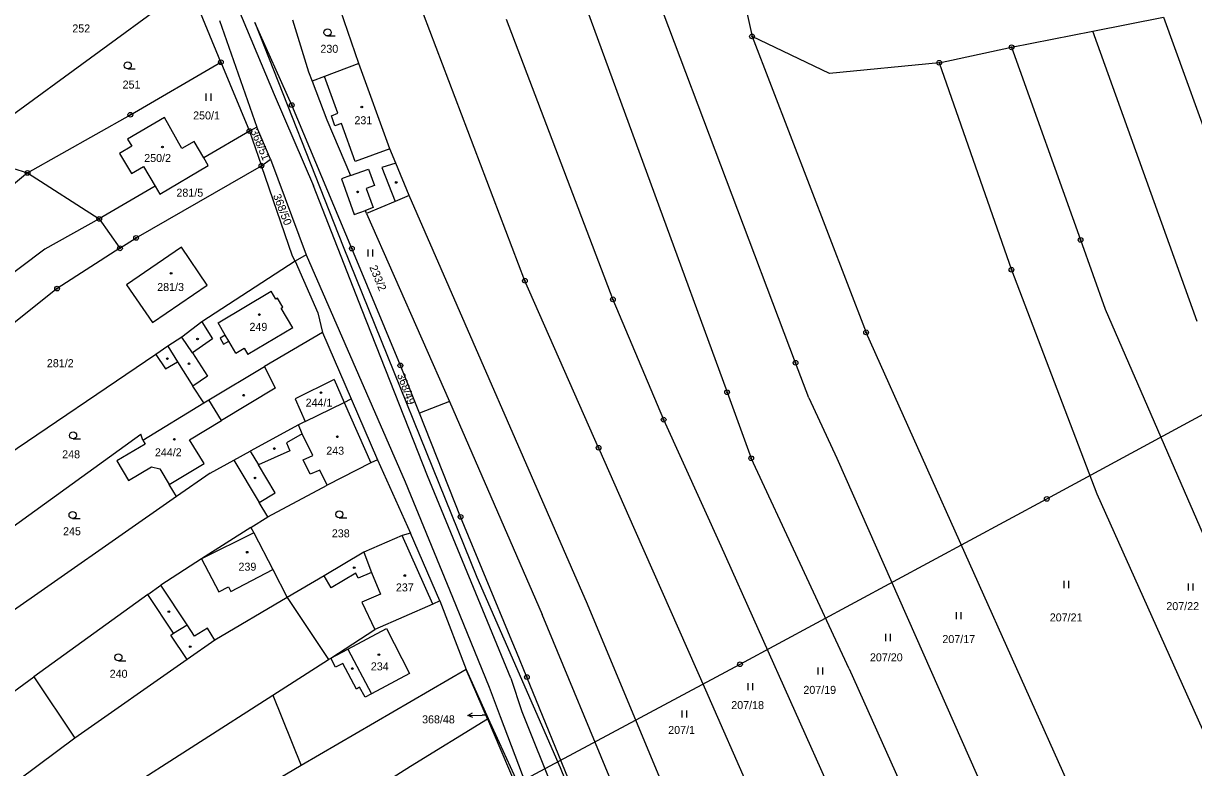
# Model space of a CAD drawing. Extents: x -762263 to -760336, y -1154405 to -1152076.
# Drawn here: x -761541.7 to -761293.1, y -1152788.2 to -1152630.1 of the extents above; entities that cross this region are included whole.
import ezdxf

# ---------------------------------------------------------------- set-up
doc = ezdxf.new("R2010")
doc.units = 0
for name, color, linetype in [('Vrstva 1', 7, 'Continuous'), ('Vrstva 12', 7, 'Continuous'), ('Vrstva 16', 7, 'Continuous'), ('Vrstva 18', 7, 'Continuous'), ('Vrstva 19', 7, 'Continuous'), ('Vrstva 24', 7, 'Continuous'), ('Vrstva 25', 7, 'Continuous'), ('Vrstva 26', 7, 'Continuous'), ('Vrstva 4', 7, 'Continuous'), ('Vrstva 6', 7, 'Continuous')]:
    doc.layers.add(name, color=color, linetype=linetype)

msp = doc.modelspace()

# ---------------------------------------------------------------- linework, layer by layer
at = {"layer": 'Vrstva 1'}
for p, q in [((-761506.46, -1152622.12), (-761545.06, -1152650.41)), ((-761499.73, -1152638.35), (-761506.46, -1152622.12)), ((-761470.41, -1152638.61), (-761474.34, -1152627.29)), ((-761484.68, -1152647.45), (-761492.49, -1152629.91)), ((-761492.49, -1152629.91), (-761473.79, -1152677.53)), ((-761484.52, -1152629.33), (-761481.11, -1152640.38)), ((-761518.97, -1152649.52), (-761499.73, -1152638.35)), ((-761499.73, -1152638.35), (-761493.66, -1152653)), ((-761470.41, -1152638.61), (-761477.69, -1152641.39)), ((-761463.81, -1152656.76), (-761470.41, -1152638.61)), ((-761481.11, -1152640.38), (-761480.35, -1152642.4)), ((-761477.69, -1152641.39), (-761480.35, -1152642.4)), ((-761480.35, -1152642.4), (-761477.25, -1152650.6)), ((-761471.9, -1152677.93), (-761484.68, -1152647.45)), ((-761540.81, -1152661.88), (-761518.97, -1152649.52)), ((-761511.7, -1152650.12), (-761519.55, -1152654.73)), ((-761508.02, -1152656.7), (-761511.7, -1152650.12)), ((-761477.25, -1152650.6), (-761472.2, -1152662.45)), ((-761493.66, -1152653), (-761503.38, -1152658.68)), ((-761492.09, -1152652.18), (-761493.66, -1152653)), ((-761493.66, -1152653), (-761491.13, -1152660.34)), ((-761489.17, -1152658.94), (-761492.09, -1152652.18)), ((-761519.55, -1152654.73), (-761518.68, -1152656.19)), ((-761505.4, -1152655.23), (-761508.02, -1152656.7)), ((-761503.38, -1152658.68), (-761505.4, -1152655.23)), ((-761554.48, -1152657.55), (-761540.81, -1152661.88)), ((-761518.68, -1152656.19), (-761521.29, -1152657.71)), ((-761521.29, -1152657.71), (-761518.76, -1152662.01)), ((-761462.56, -1152659.79), (-761463.81, -1152656.76)), ((-761518.76, -1152662.01), (-761516.17, -1152660.49)), ((-761517.74, -1152675.69), (-761491.13, -1152660.34)), ((-761516.17, -1152660.49), (-761513.7, -1152664.7)), ((-761512.73, -1152666.35), (-761502.42, -1152660.31)), ((-761502.42, -1152660.31), (-761503.38, -1152658.68)), ((-761491.13, -1152660.34), (-761489.17, -1152658.94)), ((-761484.52, -1152679.56), (-761491.13, -1152660.34)), ((-761489.17, -1152658.94), (-761481.59, -1152679.26)), ((-761459.73, -1152666.69), (-761462.56, -1152659.79)), ((-761540.81, -1152661.88), (-761525.57, -1152671.64)), ((-761472.2, -1152662.45), (-761474.13, -1152663.15)), ((-761474.13, -1152663.15), (-761471.39, -1152670.71)), ((-761513.7, -1152664.7), (-761525.57, -1152671.64)), ((-761513.7, -1152664.7), (-761512.73, -1152666.35)), ((-761462.71, -1152667.95), (-761468.8, -1152670.52)), ((-761459.73, -1152666.69), (-761462.71, -1152667.95)), ((-761421.84, -1152753.46), (-761459.73, -1152666.69)), ((-761471.39, -1152670.71), (-761469.04, -1152669.85)), ((-761468.8, -1152670.52), (-761469.04, -1152669.85)), ((-761468.8, -1152670.52), (-761451.14, -1152710.42)), ((-761525.57, -1152671.64), (-761521.17, -1152677.89)), ((-761521.17, -1152677.89), (-761517.74, -1152675.69)), ((-761521.17, -1152677.89), (-761534.53, -1152686.45)), ((-761508.11, -1152677.67), (-761519.77, -1152685.63)), ((-761502.62, -1152685.71), (-761508.11, -1152677.67)), ((-761473.79, -1152677.53), (-761445.33, -1152747.77)), ((-761461.61, -1152702.77), (-761471.9, -1152677.93)), ((-761483.96, -1152680.59), (-761503.77, -1152693.49)), ((-761483.96, -1152680.59), (-761484.52, -1152679.56)), ((-761481.59, -1152679.26), (-761483.96, -1152680.59)), ((-761483.96, -1152680.59), (-761479.15, -1152691.61)), ((-761519.77, -1152685.63), (-761514.27, -1152693.67)), ((-761514.27, -1152693.67), (-761502.62, -1152685.71)), ((-761534.53, -1152686.45), (-761560.58, -1152707.21)), ((-761479.15, -1152691.61), (-761478.16, -1152695.75)), ((-761503.77, -1152693.49), (-761508.04, -1152696.73)), ((-761478.16, -1152695.75), (-761490.45, -1152703.03)), ((-761478.16, -1152695.75), (-761472.08, -1152709.85)), ((-761508.04, -1152696.73), (-761510.99, -1152698.71)), ((-761513.57, -1152700.44), (-761563.12, -1152733.98)), ((-761510.99, -1152698.71), (-761513.57, -1152700.44)), ((-761513.57, -1152700.44), (-761511.51, -1152703.52)), ((-761511.51, -1152703.52), (-761508.97, -1152701.97)), ((-761508.97, -1152701.97), (-761505.66, -1152707.14)), ((-761502.27, -1152710.07), (-761490.45, -1152703.03)), ((-761457.57, -1152712.91), (-761461.61, -1152702.77)), ((-761503.36, -1152710.73), (-761505.66, -1152707.14)), ((-761516.34, -1152718.66), (-761503.36, -1152710.73)), ((-761503.36, -1152710.73), (-761502.27, -1152710.07)), ((-761499.64, -1152714.46), (-761502.27, -1152710.07)), ((-761481.83, -1152714.68), (-761473.56, -1152710.64)), ((-761473.56, -1152710.64), (-761472.08, -1152709.85)), ((-761472.08, -1152709.85), (-761466.43, -1152722.79)), ((-761451.14, -1152710.42), (-761457.57, -1152712.91)), ((-761451.14, -1152710.42), (-761431.48, -1152755.68)), ((-761448.8, -1152734.95), (-761457.57, -1152712.91)), ((-761506.42, -1152718.54), (-761499.64, -1152714.46)), ((-761483.25, -1152715.38), (-761493.53, -1152721)), ((-761481.83, -1152714.68), (-761483.25, -1152715.38)), ((-761555.22, -1152745.2), (-761516.73, -1152717.36)), ((-761516.34, -1152718.66), (-761516.73, -1152717.36)), ((-761515.84, -1152719.49), (-761521.87, -1152723.06)), ((-761516.34, -1152718.66), (-761515.84, -1152719.49)), ((-761503.32, -1152723.63), (-761506.42, -1152718.54)), ((-761521.87, -1152723.06), (-761519.36, -1152727.23)), ((-761502.03, -1152725.64), (-761496.96, -1152722.92)), ((-761496.96, -1152722.92), (-761493.53, -1152721)), ((-761496.96, -1152722.92), (-761491.61, -1152731.86)), ((-761466.43, -1152722.79), (-761467.9, -1152723.49)), ((-761466.43, -1152722.79), (-761459.46, -1152738.38)), ((-761519.36, -1152727.23), (-761514.47, -1152724.28)), ((-761514.47, -1152724.28), (-761512.72, -1152724.71)), ((-761512.72, -1152724.71), (-761510.71, -1152728.06)), ((-761510.71, -1152728.06), (-761503.32, -1152723.63)), ((-761502.03, -1152725.64), (-761509.17, -1152730.62)), ((-761467.9, -1152723.49), (-761477.17, -1152728.21)), ((-761509.17, -1152730.62), (-761510.71, -1152728.06)), ((-761509.17, -1152730.62), (-761546.71, -1152756.81)), ((-761489.77, -1152734.93), (-761477.17, -1152728.21)), ((-761489.77, -1152734.93), (-761491.61, -1152731.86)), ((-761493.34, -1152737.22), (-761489.77, -1152734.93)), ((-761437.9, -1152761.3), (-761448.8, -1152734.95)), ((-761493.34, -1152737.22), (-761503.85, -1152743.84)), ((-761493.34, -1152737.22), (-761492.77, -1152738.31)), ((-761492.77, -1152738.31), (-761488.69, -1152746.14)), ((-761461.22, -1152738.9), (-761469.36, -1152742.46)), ((-761459.46, -1152738.38), (-761461.22, -1152738.9)), ((-761453.19, -1152752.8), (-761459.46, -1152738.38)), ((-761469.36, -1152742.46), (-761477.8, -1152747.44)), ((-761503.85, -1152743.84), (-761512.5, -1152749.48)), ((-761488.69, -1152746.14), (-761485.62, -1152752.04)), ((-761477.8, -1152747.44), (-761485.62, -1152752.04)), ((-761445.33, -1152747.77), (-761427.68, -1152788.2)), ((-761515.26, -1152751.46), (-761512.5, -1152749.48)), ((-761515.26, -1152751.46), (-761539.5, -1152768.89)), ((-761509.8, -1152759.68), (-761515.26, -1152751.46)), ((-761485.62, -1152752.04), (-761500.99, -1152761.1)), ((-761485.62, -1152752.04), (-761476.85, -1152765.21)), ((-761453.19, -1152752.8), (-761454.73, -1152753.5)), ((-761453.19, -1152752.8), (-761447.62, -1152767.33)), ((-761454.73, -1152753.5), (-761467, -1152758.9)), ((-761359.06, -1152904.05), (-761421.84, -1152753.46)), ((-761365.51, -1152914.59), (-761431.48, -1152755.68)), ((-761510.34, -1152760.04), (-761509.8, -1152759.68)), ((-761506.89, -1152765.23), (-761510.34, -1152760.04)), ((-761476.41, -1152764.98), (-761467, -1152758.9)), ((-761500.99, -1152761.1), (-761506.89, -1152765.23)), ((-761436.95, -1152763.59), (-761437.9, -1152761.3)), ((-761506.89, -1152765.23), (-761530.76, -1152781.96)), ((-761488.72, -1152772.8), (-761476.85, -1152765.21)), ((-761476.85, -1152765.21), (-761476.41, -1152764.98)), ((-761434.72, -1152768.97), (-761436.95, -1152763.59)), ((-761447.62, -1152767.33), (-761482.68, -1152787.79)), ((-761443.12, -1152777.85), (-761447.62, -1152767.33)), ((-761447.62, -1152767.33), (-761442.95, -1152777.74)), ((-761647.74, -1152848.64), (-761539.5, -1152768.89)), ((-761539.5, -1152768.89), (-761530.76, -1152781.96)), ((-761421.27, -1152801.84), (-761434.72, -1152768.97)), ((-761522.15, -1152794.2), (-761488.72, -1152772.8)), ((-761488.72, -1152772.8), (-761482.68, -1152787.79)), ((-761443.12, -1152777.85), (-761442.95, -1152777.74)), ((-761443.12, -1152777.85), (-761437.22, -1152791.63)), ((-761442.95, -1152777.74), (-761436.7, -1152791.39)), ((-761530.76, -1152781.96), (-761631.52, -1152856.45)), ((-761482.68, -1152787.79), (-761513.77, -1152805.94)), ((-761427.68, -1152788.2), (-761402.97, -1152847.56))]:
    msp.add_line(p, q, dxfattribs=at)
at = {"layer": 'Vrstva 12'}
for p, q in [((-761324.27, -1152731.12), (-761256.42, -1152694.28)), ((-761389.45, -1152766.26), (-761324.27, -1152731.12)), ((-761450.93, -1152799.12), (-761389.45, -1152766.26))]:
    msp.add_line(p, q, dxfattribs=at)
at = {"layer": 'Vrstva 16'}
for p in [(-761447.24, -1152777.106), (-761443.36, -1152777.05)]:
    msp.add_line(p, (-761444.24, -1152777.06), dxfattribs=at)
msp.add_lwpolyline([(-761446.232, -1152777.59), (-761447.24, -1152777.106), (-761446.247, -1152776.59)], dxfattribs=at)
at = {"layer": 'Vrstva 24'}
for centre, radius in [((-761386.9, -1152632.87), 0.5), ((-761386.9, -1152632.87), 0.1), ((-761331.76, -1152635.19), 0.5), ((-761331.76, -1152635.19), 0.1), ((-761499.73, -1152638.35), 0.5), ((-761499.73, -1152638.35), 0.1), ((-761347.12, -1152638.48), 0.5), ((-761347.12, -1152638.48), 0.1), ((-761484.68, -1152647.45), 0.5), ((-761484.68, -1152647.45), 0.1), ((-761518.97, -1152649.52), 0.5), ((-761518.97, -1152649.52), 0.1), ((-761493.66, -1152653), 0.5), ((-761493.66, -1152653), 0.1), ((-761491.13, -1152660.34), 0.5), ((-761491.13, -1152660.34), 0.1), ((-761540.81, -1152661.88), 0.5), ((-761540.81, -1152661.88), 0.1), ((-761525.57, -1152671.64), 0.5), ((-761525.57, -1152671.64), 0.1), ((-761517.74, -1152675.69), 0.5), ((-761517.74, -1152675.69), 0.1), ((-761317.11, -1152676.11), 0.5), ((-761521.17, -1152677.89), 0.5), ((-761521.17, -1152677.89), 0.1), ((-761471.9, -1152677.93), 0.5), ((-761471.9, -1152677.93), 0.1), ((-761317.11, -1152676.11), 0.1), ((-761331.78, -1152682.43), 0.5), ((-761331.78, -1152682.43), 0.1), ((-761435.14, -1152684.79), 0.5), ((-761435.14, -1152684.79), 0.1), ((-761534.53, -1152686.45), 0.5), ((-761534.53, -1152686.45), 0.1), ((-761416.45, -1152688.73), 0.5), ((-761416.45, -1152688.73), 0.1), ((-761362.65, -1152695.74), 0.5), ((-761362.65, -1152695.74), 0.1), ((-761461.61, -1152702.77), 0.5), ((-761461.61, -1152702.77), 0.1), ((-761377.65, -1152702.21), 0.5), ((-761377.65, -1152702.21), 0.1), ((-761392.18, -1152708.47), 0.5), ((-761392.18, -1152708.47), 0.1), ((-761405.67, -1152714.29), 0.5), ((-761405.67, -1152714.29), 0.1), ((-761419.51, -1152720.25), 0.5), ((-761419.51, -1152720.25), 0.1), ((-761387.07, -1152722.49), 0.5), ((-761387.07, -1152722.49), 0.1), ((-761448.8, -1152734.95), 0.5), ((-761448.8, -1152734.95), 0.1), ((-761434.72, -1152768.97), 0.5), ((-761434.72, -1152768.97), 0.1)]:
    msp.add_circle(centre, radius, dxfattribs=at)
at = {"layer": 'Vrstva 25'}
for p, q in [((-761477.08, -1152632.78), (-761475.48, -1152632.78)), ((-761519.52, -1152639.78), (-761517.92, -1152639.78)), ((-761502.83, -1152646.53), (-761502.83, -1152645.03)), ((-761501.83, -1152646.53), (-761501.83, -1152645.03)), ((-761468.48, -1152679.62), (-761468.48, -1152678.12)), ((-761467.48, -1152679.62), (-761467.48, -1152678.12)), ((-761531.13, -1152718.38), (-761529.53, -1152718.38)), ((-761531.25, -1152735.29), (-761529.65, -1152735.29)), ((-761474.58, -1152735.16), (-761472.98, -1152735.16)), ((-761320.59, -1152750.06), (-761320.59, -1152748.56)), ((-761319.59, -1152750.06), (-761319.59, -1152748.56)), ((-761294.2, -1152750.56), (-761294.2, -1152749.06)), ((-761293.2, -1152750.56), (-761293.2, -1152749.06)), ((-761343.46, -1152756.7), (-761343.46, -1152755.2)), ((-761342.46, -1152756.7), (-761342.46, -1152755.2)), ((-761358.48, -1152761.32), (-761358.48, -1152759.82)), ((-761357.48, -1152761.32), (-761357.48, -1152759.82)), ((-761521.5, -1152765.53), (-761519.9, -1152765.53)), ((-761372.86, -1152768.46), (-761372.86, -1152766.96)), ((-761371.86, -1152768.46), (-761371.86, -1152766.96)), ((-761387.72, -1152771.76), (-761387.72, -1152770.26)), ((-761386.72, -1152771.76), (-761386.72, -1152770.26)), ((-761401.71, -1152777.57), (-761401.71, -1152776.07)), ((-761400.71, -1152777.57), (-761400.71, -1152776.07))]:
    msp.add_line(p, q, dxfattribs=at)
for centre, radius in [((-761477.08, -1152632.03), 0.75), ((-761519.52, -1152639.03), 0.75), ((-761469.8, -1152647.88), 0.175), ((-761512.15, -1152656.38), 0.175), ((-761470.69, -1152665.9), 0.175), ((-761462.49, -1152663.89), 0.175), ((-761510.31, -1152683.21), 0.175), ((-761491.55, -1152691.96), 0.175), ((-761504.69, -1152697.14), 0.175), ((-761511.11, -1152701.32), 0.175), ((-761506.5, -1152702.42), 0.175), ((-761494.88, -1152709.09), 0.175), ((-761478.46, -1152708.55), 0.175), ((-761531.13, -1152717.63), 0.75), ((-761474.99, -1152717.93), 0.175), ((-761509.62, -1152718.46), 0.175), ((-761488.37, -1152720.43), 0.175), ((-761492.48, -1152726.68), 0.175), ((-761531.25, -1152734.54), 0.75), ((-761474.58, -1152734.41), 0.75), ((-761494.15, -1152742.45), 0.175), ((-761471.41, -1152745.74), 0.175), ((-761460.66, -1152747.41), 0.175), ((-761510.79, -1152755.08), 0.175), ((-761506.25, -1152762.51), 0.175), ((-761521.5, -1152764.78), 0.75), ((-761466.17, -1152764.22), 0.175), ((-761471.81, -1152767.17), 0.175)]:
    msp.add_circle(centre, radius, dxfattribs=at)
at = {"layer": 'Vrstva 26'}
for centre in [(-761324.27, -1152731.12), (-761389.45, -1152766.26)]:
    msp.add_circle(centre, 0.5, dxfattribs=at)
at = {"layer": 'Vrstva 4'}
for p, q in [((-761506.1, -1152602.75), (-761488.43, -1152645.22)), ((-761500.02, -1152629.46), (-761492.09, -1152652.18)), ((-761474.87, -1152649.21), (-761477.69, -1152641.39)), ((-761488.43, -1152645.22), (-761480.07, -1152664.59)), ((-761476.26, -1152649.71), (-761474.87, -1152649.21)), ((-761475.5, -1152651.9), (-761476.26, -1152649.71)), ((-761474.09, -1152651.4), (-761475.5, -1152651.9)), ((-761471.19, -1152659.44), (-761474.09, -1152651.4)), ((-761463.81, -1152656.76), (-761471.19, -1152659.44)), ((-761472.2, -1152662.45), (-761468.35, -1152661.05)), ((-761468.35, -1152661.05), (-761467.07, -1152664.56)), ((-761462.56, -1152659.79), (-761465.55, -1152660.73)), ((-761465.55, -1152660.73), (-761462.71, -1152667.95)), ((-761469.73, -1152691.04), (-761480.07, -1152664.59)), ((-761467.07, -1152664.56), (-761468.85, -1152665.21)), ((-761468.85, -1152665.21), (-761467.38, -1152669.25)), ((-761467.38, -1152669.25), (-761469.04, -1152669.85)), ((-761481.59, -1152679.26), (-761460.57, -1152727.53)), ((-761500.34, -1152693.71), (-761489.05, -1152687)), ((-761488.05, -1152688.69), (-761489.05, -1152687)), ((-761487.69, -1152688.48), (-761488.05, -1152688.69)), ((-761486.56, -1152690.39), (-761487.69, -1152688.48)), ((-761486.92, -1152690.6), (-761486.56, -1152690.39)), ((-761484.46, -1152694.76), (-761486.92, -1152690.6)), ((-761455.83, -1152726.19), (-761469.73, -1152691.04)), ((-761503.77, -1152693.49), (-761501.5, -1152697.14)), ((-761498.8, -1152696.34), (-761500.34, -1152693.71)), ((-761484.46, -1152694.76), (-761494.01, -1152700.42)), ((-761505.75, -1152700.07), (-761508.04, -1152696.73)), ((-761501.5, -1152697.14), (-761505.75, -1152700.07)), ((-761498.8, -1152696.34), (-761499.92, -1152696.99)), ((-761499.92, -1152696.99), (-761499.19, -1152698.24)), ((-761499.19, -1152698.24), (-761498.07, -1152697.59)), ((-761498.07, -1152697.59), (-761498.8, -1152696.34)), ((-761496.57, -1152700.14), (-761498.07, -1152697.59)), ((-761510.99, -1152698.71), (-761508.97, -1152701.97)), ((-761505.75, -1152700.07), (-761502.57, -1152705.07)), ((-761496.57, -1152700.14), (-761494.81, -1152699.13)), ((-761494.81, -1152699.13), (-761494.01, -1152700.42)), ((-761490.45, -1152703.03), (-761488.18, -1152707.63)), ((-761502.57, -1152705.07), (-761505.66, -1152707.14)), ((-761475.7, -1152705.79), (-761483.96, -1152709.87)), ((-761475.7, -1152705.79), (-761473.56, -1152710.64)), ((-761488.18, -1152707.63), (-761499.64, -1152714.46)), ((-761483.96, -1152709.87), (-761481.83, -1152714.68)), ((-761473.56, -1152710.64), (-761467.9, -1152723.49)), ((-761482.45, -1152717.3), (-761483.25, -1152715.38)), ((-761482.45, -1152717.3), (-761485.8, -1152719.18)), ((-761480.23, -1152721.89), (-761482.45, -1152717.3)), ((-761485.8, -1152719.18), (-761485.12, -1152720.93)), ((-761493.53, -1152721), (-761491.71, -1152723.87)), ((-761485.12, -1152720.93), (-761491.71, -1152723.87)), ((-761482.26, -1152722.81), (-761480.23, -1152721.89)), ((-761480.77, -1152725.9), (-761482.26, -1152722.81)), ((-761488.22, -1152729.83), (-761491.71, -1152723.87)), ((-761478.73, -1152725), (-761480.77, -1152725.9)), ((-761477.17, -1152728.21), (-761478.73, -1152725)), ((-761460.57, -1152727.53), (-761450.54, -1152751.97)), ((-761438.16, -1152769.18), (-761455.83, -1152726.19)), ((-761491.61, -1152731.86), (-761488.22, -1152729.83)), ((-761492.77, -1152738.31), (-761503.85, -1152743.84)), ((-761454.73, -1152753.5), (-761461.22, -1152738.9)), ((-761469.36, -1152742.46), (-761467.76, -1152746.74)), ((-761503.85, -1152743.84), (-761500.2, -1152750.9)), ((-761497.6, -1152750.78), (-761488.69, -1152746.14)), ((-761476.28, -1152750.01), (-761477.8, -1152747.44)), ((-761471.04, -1152746.9), (-761476.28, -1152750.01)), ((-761470.55, -1152747.99), (-761471.04, -1152746.9)), ((-761467.76, -1152746.74), (-761470.55, -1152747.99)), ((-761467.76, -1152746.74), (-761465.81, -1152751.36)), ((-761506.92, -1152757.89), (-761512.5, -1152749.48)), ((-761500.2, -1152750.9), (-761498.11, -1152749.81)), ((-761498.11, -1152749.81), (-761497.6, -1152750.78)), ((-761465.81, -1152751.36), (-761469.81, -1152753.09)), ((-761450.54, -1152751.97), (-761442.76, -1152771.15)), ((-761469.81, -1152753.09), (-761467, -1152758.9)), ((-761509.8, -1152759.68), (-761506.92, -1152757.89)), ((-761505.33, -1152760.29), (-761506.92, -1152757.89)), ((-761502.6, -1152758.6), (-761505.33, -1152760.29)), ((-761500.99, -1152761.1), (-761502.6, -1152758.6)), ((-761472.75, -1152763.03), (-761464.56, -1152758.66)), ((-761464.56, -1152758.66), (-761459.64, -1152768.21)), ((-761476.41, -1152764.98), (-761472.75, -1152763.03)), ((-761475.37, -1152766.89), (-761476.41, -1152764.98)), ((-761472.75, -1152763.03), (-761467.73, -1152772.54)), ((-761473.86, -1152766.07), (-761475.37, -1152766.89)), ((-761470.93, -1152771.52), (-761473.86, -1152766.07)), ((-761459.64, -1152768.21), (-761467.73, -1152772.54)), ((-761438.16, -1152769.18), (-761435.81, -1152776.3)), ((-761470.28, -1152771.14), (-761470.93, -1152771.52)), ((-761469.09, -1152773.27), (-761470.28, -1152771.14)), ((-761467.73, -1152772.54), (-761469.09, -1152773.27)), ((-761442.76, -1152771.15), (-761440.38, -1152777.38)), ((-761440.38, -1152777.38), (-761430.06, -1152804.55)), ((-761435.81, -1152776.3), (-761364.68, -1152952.56))]:
    msp.add_line(p, q, dxfattribs=at)
at = {"layer": 'Vrstva 6'}
for p, q in [((-761377.65, -1152702.21), (-761410.58, -1152615.08)), ((-761425.37, -1152617.92), (-761392.18, -1152708.47)), ((-761389.82, -1152619.53), (-761386.9, -1152632.87)), ((-761435.14, -1152684.79), (-761458.17, -1152624.21)), ((-761439.1, -1152629.18), (-761416.45, -1152688.73)), ((-761314.49, -1152631.78), (-761299.47, -1152628.81)), ((-761299.47, -1152628.81), (-761287.06, -1152663.15)), ((-761386.9, -1152632.87), (-761362.65, -1152695.74)), ((-761370.41, -1152640.74), (-761386.9, -1152632.87)), ((-761331.76, -1152635.19), (-761314.49, -1152631.78)), ((-761292.33, -1152693.43), (-761314.49, -1152631.78)), ((-761347.12, -1152638.48), (-761331.76, -1152635.19)), ((-761331.76, -1152635.19), (-761317.11, -1152676.11)), ((-761347.12, -1152638.48), (-761370.41, -1152640.74)), ((-761347.12, -1152638.48), (-761331.78, -1152682.43)), ((-761540.81, -1152661.88), (-761566.2, -1152682.83)), ((-761525.57, -1152671.64), (-761537.16, -1152678.07)), ((-761537.16, -1152678.07), (-761677.64, -1152783.3)), ((-761317.11, -1152676.11), (-761311.86, -1152690.78)), ((-761331.78, -1152682.43), (-761313.61, -1152730.06)), ((-761419.51, -1152720.25), (-761435.14, -1152684.79)), ((-761416.45, -1152688.73), (-761405.67, -1152714.29)), ((-761311.86, -1152690.78), (-761286.2, -1152749.91)), ((-761311.29, -1152810.33), (-761362.65, -1152695.74)), ((-761374.84, -1152709.68), (-761377.65, -1152702.21)), ((-761392.18, -1152708.47), (-761387.07, -1152722.49)), ((-761374.84, -1152709.68), (-761368.89, -1152722.5)), ((-761405.67, -1152714.29), (-761393.53, -1152741.09)), ((-761419.51, -1152720.25), (-761411.79, -1152737.78)), ((-761366.23, -1152767.2), (-761387.07, -1152722.49)), ((-761368.89, -1152722.5), (-761339, -1152790.03)), ((-761313.61, -1152730.06), (-761253.15, -1152865.22)), ((-761411.79, -1152737.78), (-761396.79, -1152771.69)), ((-761393.53, -1152741.09), (-761361.53, -1152812.56)), ((-761366.23, -1152767.2), (-761312.07, -1152888.28)), ((-761396.79, -1152771.69), (-761387.09, -1152793.76)), ((-761459.45, -1152787.9), (-761443.12, -1152777.85)), ((-761486.39, -1152804.93), (-761459.45, -1152787.9))]:
    msp.add_line(p, q, dxfattribs=at)

# ---------------------------------------------------------------- texts
at = {"layer": 'Vrstva 16'}
msp.add_text('368/48', height=1.7, dxfattribs=at).set_placement((-761456.991, -1152778.81))
at = {"layer": 'Vrstva 18'}
for s, p in [('252', (-761531.298, -1152632.03)), ('230', (-761478.593, -1152636.35)), ('251', (-761520.613, -1152643.95)), ('250/1', (-761505.632, -1152650.51)), ('281/5', (-761509.183, -1152666.92)), ('281/2', (-761536.703, -1152703.14)), ('248', (-761533.448, -1152722.5)), ('245', (-761533.265, -1152738.84)), ('238', (-761476.163, -1152739.29)), ('207/22', (-761298.87, -1152754.75)), ('207/21', (-761323.638, -1152757.15)), ('207/17', (-761346.454, -1152761.75)), ('207/20', (-761361.843, -1152765.63)), ('240', (-761523.363, -1152769.13)), ('207/19', (-761375.985, -1152772.54)), ('207/18', (-761391.305, -1152775.78)), ('207/1', (-761404.705, -1152781.06))]:
    msp.add_text(s, height=1.7, dxfattribs=at).set_placement(p)
for s, height, rotation, p in [('368/51', 1.7, 292.78143, (-761493.484, -1152652.952)), ('368/50', 1.7, 291.17715, (-761488.697, -1152666.691)), ('233/2', 1.7, 292.32307, (-761468.22, -1152681.88)), ('368/49', 1.7, 289.91664, (-761462.333, -1152704.757)), ('368/48', 0.1, 296.56296, (-761443.372, -1152777.216))]:
    msp.add_text(s, height=height, rotation=rotation, dxfattribs=at).set_placement(p)
at = {"layer": 'Vrstva 19'}
for s, p in [('231', (-761471.363, -1152651.53)), ('250/2', (-761516.024, -1152659.55)), ('281/3', (-761513.263, -1152686.96)), ('249', (-761493.663, -1152695.42)), ('244/1', (-761481.733, -1152711.53)), ('244/2', (-761513.75, -1152722.08)), ('243', (-761477.345, -1152721.73)), ('239', (-761495.993, -1152746.38)), ('237', (-761462.553, -1152750.78)), ('234', (-761467.873, -1152767.55))]:
    msp.add_text(s, height=1.7, dxfattribs=at).set_placement(p)

doc.saveas('drawing.dxf')
